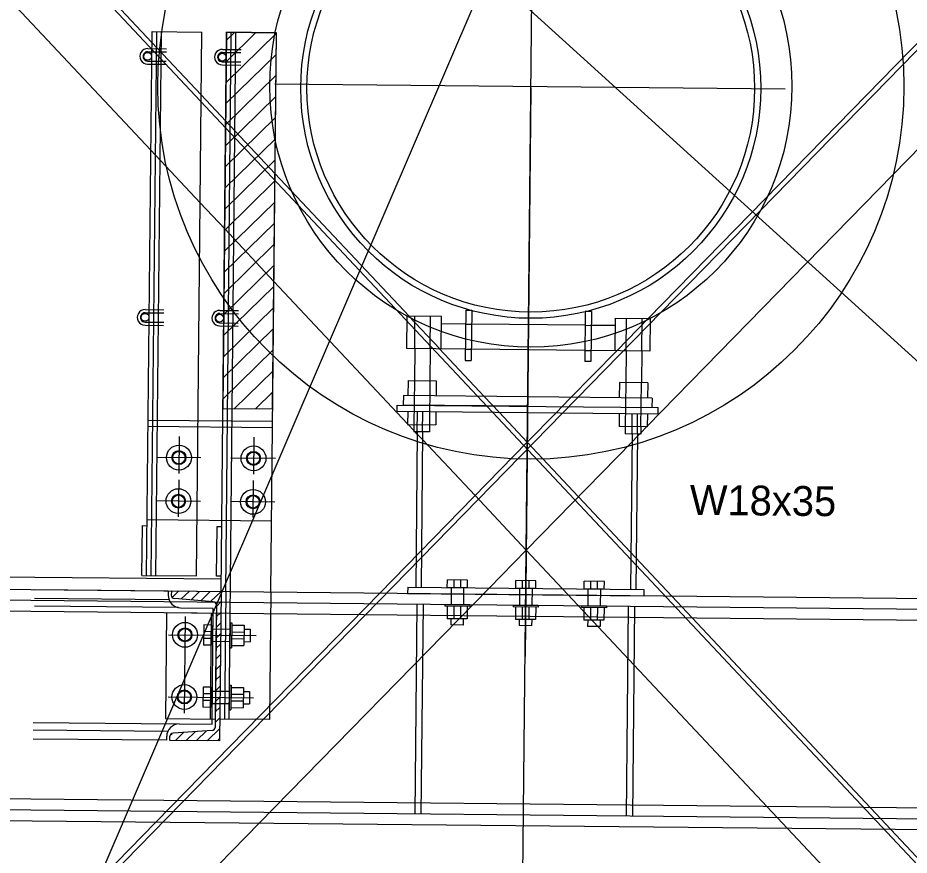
# Model space of a CAD drawing. Extents: x 632312 to 632885, y 378199 to 378534.
# Drawn here: x 632769.45 to 632775.42, y 378346.72 to 378352.33 of the extents above; entities that cross this region are included whole.
import ezdxf

# ---------------------------------------------------------------- set-up
doc = ezdxf.new("R2010")
doc.units = 0
for name, color, linetype in [('B_Boring', 7, 'Continuous'), ('BDR-SHEET_TITLE', 7, 'Continuous'), ('R_Border', 7, 'Continuous'), ('R_Proposed Const Limits', 7, 'Continuous'), ('R_Proposed Const Limits Cut', 7, 'Continuous'), ('R_Road Edge of Shoulder', 7, 'Continuous'), ('R_Wall', 7, 'Continuous'), ('SHT_Dimensions', 7, 'Continuous'), ('USACE_Easement', 7, 'Continuous')]:
    doc.layers.add(name, color=color, linetype=linetype)

msp = doc.modelspace()

# ---------------------------------------------------------------- linework, layer by layer
at = {"layer": 'B_Boring'}
for p, q in [((632770.3098, 378348.5913), (632770.346, 378352.237)), ((632770.341, 378348.591), (632770.3773, 378352.2366)), ((632770.346, 378352.237), (632770.6793, 378352.2336)), ((632770.6431, 378348.588), (632770.6793, 378352.2336)), ((632770.8087, 378348.4822), (632770.846, 378352.232)), ((632770.84, 378348.4819), (632770.8772, 378352.2317)), ((632770.8426, 378351.8956), (632771.1793, 378352.2256)), ((632770.8441, 378352.037), (632771.041, 378352.23)), ((632770.8455, 378352.1784), (632770.8996, 378352.2314)), ((632770.846, 378352.232), (632771.1793, 378352.2287)), ((632771.142, 378348.4789), (632771.1793, 378352.2287)), ((632770.3172, 378352.1226), (632770.4422, 378352.1214)), ((632770.8172, 378352.1177), (632770.9422, 378352.1164)), ((632770.317, 378352.1018), (632770.442, 378352.1006)), ((632770.817, 378352.0968), (632770.942, 378352.0956)), ((632770.8412, 378351.7542), (632771.1779, 378352.0842)), ((632770.3162, 378352.0185), (632770.4412, 378352.0172)), ((632770.3164, 378352.0393), (632770.4414, 378352.0381)), ((632770.8162, 378352.0135), (632770.9412, 378352.0123)), ((632770.8164, 378352.0343), (632770.9414, 378352.0331)), ((632770.8398, 378351.6128), (632771.1765, 378351.9428)), ((632770.8384, 378351.4713), (632771.1751, 378351.8013)), ((632770.837, 378351.3299), (632771.1737, 378351.6599)), ((632770.8356, 378351.1885), (632771.1722, 378351.5185)), ((632770.8342, 378351.0471), (632771.1708, 378351.3771)), ((632770.8328, 378350.9057), (632771.1694, 378351.2357)), ((632770.8314, 378350.7643), (632771.168, 378351.0943)), ((632770.83, 378350.6229), (632771.1666, 378350.9529)), ((632770.8286, 378350.4814), (632771.1652, 378350.8114)), ((632770.8272, 378350.34), (632771.1638, 378350.67)), ((632770.8258, 378350.1986), (632771.1624, 378350.5286)), ((632770.2998, 378350.3727), (632770.4248, 378350.3715)), ((632770.8244, 378350.0572), (632771.161, 378350.3872)), ((632770.2996, 378350.3519), (632770.4246, 378350.3507)), ((632772.0525, 378350.3285), (632772.0504, 378350.1117)), ((632772.2866, 378350.3262), (632772.0525, 378350.3285)), ((632772.2845, 378350.1094), (632772.2866, 378350.3262)), ((632772.4479, 378350.3687), (632772.4445, 378350.0328)), ((632772.4479, 378350.3687), (632772.4889, 378350.3682)), ((632772.4889, 378350.3682), (632772.4856, 378350.0324)), ((632773.2494, 378350.3607), (632773.2461, 378350.0249)), ((632773.2905, 378350.3603), (632773.2494, 378350.3607)), ((632773.2905, 378350.3603), (632773.2872, 378350.0245)), ((632773.4487, 378350.0978), (632773.4509, 378350.3146)), ((632773.4509, 378350.3146), (632773.685, 378350.3123)), ((632770.2988, 378350.2686), (632770.4238, 378350.2673)), ((632770.299, 378350.2894), (632770.424, 378350.2882)), ((632772.447, 378350.2758), (632772.2862, 378350.2774)), ((632773.2485, 378350.2678), (632772.488, 378350.2754)), ((632773.4504, 378350.2658), (632773.2896, 378350.2674)), ((632773.685, 378350.3123), (632773.6828, 378350.0955)), ((632770.823, 378349.9158), (632771.1596, 378350.2458)), ((632770.8216, 378349.7744), (632771.1582, 378350.1044)), ((632772.4453, 378350.1078), (632772.0504, 378350.1117)), ((632772.1059, 378350.1111), (632772.1038, 378349.8976)), ((632772.2107, 378350.1101), (632772.2086, 378349.8966)), ((632773.2468, 378350.0998), (632772.4864, 378350.1074)), ((632773.6828, 378350.0955), (632773.2879, 378350.0994)), ((632773.5225, 378350.0971), (632773.5204, 378349.8836)), ((632773.6273, 378350.096), (632773.6252, 378349.8825)), ((632772.4445, 378350.0328), (632772.4856, 378350.0324)), ((632773.2872, 378350.0245), (632773.2461, 378350.0249)), ((632770.8981, 378349.7094), (632771.1568, 378349.963)), ((632772.0616, 378349.8981), (632772.0606, 378349.7959)), ((632772.0616, 378349.8981), (632772.2508, 378349.8962)), ((632772.2508, 378349.8962), (632772.2497, 378349.7941)), ((632773.4782, 378349.884), (632773.4772, 378349.7819)), ((632773.6674, 378349.8821), (632773.4782, 378349.884)), ((632773.6674, 378349.8821), (632773.6663, 378349.78)), ((632771.0395, 378349.708), (632771.1554, 378349.8215)), ((632772.0302, 378349.7962), (632772.0295, 378349.733)), ((632773.6968, 378349.7797), (632772.0302, 378349.7962)), ((632773.6968, 378349.7797), (632773.6961, 378349.7165)), ((632771.9875, 378349.6918), (632771.9879, 378349.7335)), ((632771.9879, 378349.7335), (632773.7378, 378349.7161)), ((632773.7374, 378349.6744), (632773.7378, 378349.7161)), ((632771.9875, 378349.6918), (632773.7374, 378349.6744)), ((632772.0595, 378349.6911), (632772.0587, 378349.603)), ((632772.2487, 378349.6892), (632772.2478, 378349.6012)), ((632773.4761, 378349.677), (632773.4753, 378349.589)), ((632773.6653, 378349.6751), (632773.6644, 378349.5871)), ((632770.3201, 378349.6329), (632771.1534, 378349.6246)), ((632772.0587, 378349.603), (632772.2478, 378349.6012)), ((632772.1008, 378349.6026), (632772.1004, 378349.5536)), ((632772.2056, 378349.6016), (632772.2052, 378349.5526)), ((632770.3197, 378349.5912), (632771.153, 378349.583)), ((632772.2052, 378349.5526), (632772.1004, 378349.5536)), ((632772.1236, 378349.5534), (632772.1132, 378348.5109)), ((632772.159, 378349.553), (632772.1486, 378348.5105)), ((632773.6644, 378349.5871), (632773.4753, 378349.589)), ((632773.5174, 378349.5885), (632773.517, 378349.5395)), ((632773.6218, 378349.5385), (632773.517, 378349.5395)), ((632773.5631, 378349.5391), (632773.5527, 378348.4966)), ((632773.5985, 378349.5387), (632773.5882, 378348.4962)), ((632773.6222, 378349.5875), (632773.6218, 378349.5385)), ((632770.3135, 378348.9663), (632771.1468, 378348.958)), ((632770.2785, 378348.5916), (632770.2818, 378348.9249)), ((632770.2818, 378348.9249), (632770.3131, 378348.9246)), ((632770.7785, 378348.5866), (632770.7818, 378348.92)), ((632770.7818, 378348.92), (632770.8131, 378348.9196)), ((632770.8095, 378348.5655), (632768.3097, 378348.5904)), ((632770.2785, 378348.5916), (632770.6431, 378348.588)), ((632770.8097, 378348.5863), (632770.7785, 378348.5866)), ((632772.3247, 378348.5088), (632772.3252, 378348.5608)), ((632772.4606, 378348.5595), (632772.3252, 378348.5608)), ((632772.3698, 378348.5083), (632772.3703, 378348.5604)), ((632772.4149, 378348.5079), (632772.4155, 378348.5599)), ((632772.4601, 378348.5074), (632772.4606, 378348.5595)), ((632772.783, 378348.5042), (632772.7835, 378348.5563)), ((632772.9189, 378348.5549), (632772.7835, 378348.5563)), ((632772.8281, 378348.5038), (632772.8286, 378348.5558)), ((632772.8733, 378348.5033), (632772.8738, 378348.5554)), ((632772.9184, 378348.5029), (632772.9189, 378348.5549)), ((632773.2413, 378348.4996), (632773.2418, 378348.5517)), ((632773.3772, 378348.5504), (632773.2418, 378348.5517)), ((632773.2864, 378348.4992), (632773.287, 378348.5513)), ((632773.3316, 378348.4988), (632773.3321, 378348.5508)), ((632773.3767, 378348.4983), (632773.3772, 378348.5504)), ((632778.35, 378348.4072), (632767.3505, 378348.5165)), ((632770.4539, 378348.4857), (632769.5588, 378348.4946)), ((632770.4539, 378348.4857), (632770.4537, 378348.4586)), ((632770.4754, 378348.4855), (632770.4752, 378348.4584)), ((632770.8087, 378348.4822), (632770.4754, 378348.4855)), ((632770.4811, 378348.4436), (632770.5234, 378348.485)), ((632770.542, 378348.4332), (632770.5941, 378348.4843)), ((632770.6074, 378348.4273), (632770.6648, 378348.4836)), ((632770.6729, 378348.4214), (632770.7355, 378348.4829)), ((632770.7383, 378348.4156), (632770.8063, 378348.4822)), ((632770.8087, 378348.4822), (632770.7988, 378347.4822)), ((632772.0591, 378348.5114), (632772.0587, 378348.4697)), ((632772.0587, 378348.4697), (632773.6419, 378348.454)), ((632772.0591, 378348.5114), (632773.6423, 378348.4957)), ((632772.4601, 378348.5074), (632772.3247, 378348.5088)), ((632772.3507, 378348.5085), (632772.3496, 378348.3943)), ((632772.434, 378348.5077), (632772.4329, 378348.3935)), ((632772.9184, 378348.5029), (632772.783, 378348.5042)), ((632772.809, 378348.5039), (632772.8079, 378348.3898)), ((632772.8924, 378348.5031), (632772.8912, 378348.389)), ((632773.3767, 378348.4983), (632773.2413, 378348.4996)), ((632773.2673, 378348.4994), (632773.2662, 378348.3852)), ((632773.3507, 378348.4986), (632773.3495, 378348.3844)), ((632773.6423, 378348.4957), (632773.6419, 378348.454)), ((632778.3493, 378348.3347), (632767.3498, 378348.4441)), ((632770.4594, 378348.4273), (632769.5582, 378348.4363)), ((632770.7564, 378348.4139), (632770.4957, 378348.4374)), ((632770.7769, 378348.3834), (632770.808, 378348.4139)), ((632770.5362, 378348.3745), (632770.7559, 378348.3723)), ((632770.7482, 378347.5931), (632770.7559, 378348.3723)), ((632770.777, 378348.3929), (632770.7688, 378347.5721)), ((632770.7762, 378348.3127), (632770.8073, 378348.3432)), ((632772.3079, 378348.3948), (632772.3078, 378348.3843)), ((632772.4745, 378348.3827), (632772.3078, 378348.3843)), ((632772.4746, 378348.3931), (632772.3079, 378348.3948)), ((632772.3234, 378348.3842), (632772.3226, 378348.3009)), ((632772.3686, 378348.3837), (632772.3677, 378348.3004)), ((632772.4137, 378348.3833), (632772.4129, 378348.3)), ((632772.4588, 378348.3828), (632772.458, 378348.2995)), ((632772.4746, 378348.3931), (632772.4745, 378348.3827)), ((632772.7662, 378348.3902), (632772.7661, 378348.3798)), ((632772.9328, 378348.3781), (632772.7661, 378348.3798)), ((632772.9329, 378348.3885), (632772.7662, 378348.3902)), ((632772.7818, 378348.3796), (632772.7809, 378348.2963)), ((632772.8269, 378348.3792), (632772.8261, 378348.2959)), ((632772.872, 378348.3787), (632772.8712, 378348.2954)), ((632772.9171, 378348.3783), (632772.9163, 378348.295)), ((632772.9329, 378348.3885), (632772.9328, 378348.3781)), ((632773.2245, 378348.3856), (632773.2244, 378348.3752)), ((632773.3911, 378348.3736), (632773.2244, 378348.3752)), ((632773.3912, 378348.384), (632773.2245, 378348.3856)), ((632773.2401, 378348.3751), (632773.2392, 378348.2917)), ((632773.2852, 378348.3746), (632773.2844, 378348.2913)), ((632773.3303, 378348.3742), (632773.3295, 378348.2908)), ((632773.3755, 378348.3737), (632773.3746, 378348.2904)), ((632773.3912, 378348.384), (632773.3911, 378348.3736)), ((632770.4431, 378348.34), (632770.4361, 378347.6317)), ((632770.7764, 378348.3366), (632770.4431, 378348.34)), ((632770.7382, 378347.6287), (632770.7452, 378348.337)), ((632770.7764, 378348.3366), (632770.7694, 378347.6283)), ((632772.458, 378348.2995), (632772.3226, 378348.3009)), ((632772.3486, 378348.3006), (632772.3482, 378348.2589)), ((632772.432, 378348.2998), (632772.4316, 378348.2581)), ((632772.9163, 378348.295), (632772.7809, 378348.2963)), ((632772.807, 378348.296), (632772.8065, 378348.2544)), ((632772.8903, 378348.2952), (632772.8899, 378348.2535)), ((632773.3746, 378348.2904), (632773.2392, 378348.2917)), ((632773.2653, 378348.2915), (632773.2649, 378348.2498)), ((632773.3486, 378348.2907), (632773.3482, 378348.249)), ((632770.6924, 378348.2593), (632770.691, 378348.124)), ((632770.7445, 378348.2588), (632770.6924, 378348.2593)), ((632770.7445, 378348.2588), (632770.7431, 378348.1234)), ((632770.7755, 378348.242), (632770.8066, 378348.2725)), ((632770.8691, 378348.2732), (632770.8675, 378348.1066)), ((632770.8691, 378348.2732), (632770.8796, 378348.2731)), ((632770.8796, 378348.2731), (632770.8779, 378348.1065)), ((632770.8794, 378348.2575), (632770.9627, 378348.2567)), ((632770.9627, 378348.2567), (632770.9614, 378348.1213)), ((632770.9625, 378348.2306), (632771.0041, 378348.2302)), ((632771.0041, 378348.2302), (632771.0033, 378348.1469)), ((632772.4316, 378348.2581), (632772.3482, 378348.2589)), ((632772.8899, 378348.2535), (632772.8065, 378348.2544)), ((632773.3482, 378348.249), (632773.2649, 378348.2498)), ((632770.7436, 378348.1686), (632770.6915, 378348.1691)), ((632770.744, 378348.2137), (632770.6919, 378348.2142)), ((632770.7748, 378348.1713), (632770.8059, 378348.2018)), ((632770.8785, 378348.1672), (632770.9618, 378348.1664)), ((632770.8789, 378348.2124), (632770.9623, 378348.2115)), ((632770.7431, 378348.1234), (632770.691, 378348.124)), ((632770.7741, 378348.1006), (632770.8052, 378348.1311)), ((632770.8675, 378348.1066), (632770.8779, 378348.1065)), ((632770.8781, 378348.1221), (632770.9614, 378348.1213)), ((632770.9616, 378348.1473), (632771.0033, 378348.1469)), ((632770.7734, 378348.0299), (632770.8045, 378348.0604)), ((632770.7727, 378347.9592), (632770.8038, 378347.9897)), ((632770.772, 378347.8884), (632770.8031, 378347.919)), ((632770.6882, 378347.8427), (632770.6869, 378347.7073)), ((632770.7403, 378347.8422), (632770.6882, 378347.8427)), ((632770.7403, 378347.8422), (632770.739, 378347.7068)), ((632770.7713, 378347.8177), (632770.8024, 378347.8483)), ((632770.865, 378347.8566), (632770.8633, 378347.6899)), ((632770.865, 378347.8566), (632770.8754, 378347.8565)), ((632770.8754, 378347.8565), (632770.8738, 378347.6898)), ((632770.8753, 378347.8408), (632770.9586, 378347.84)), ((632770.9586, 378347.84), (632770.9572, 378347.7046)), ((632770.9583, 378347.814), (632771, 378347.8136)), ((632771, 378347.8136), (632770.9992, 378347.7302)), ((632770.7394, 378347.7519), (632770.6873, 378347.7524)), ((632770.7399, 378347.7971), (632770.6878, 378347.7976)), ((632770.7706, 378347.747), (632770.8017, 378347.7776)), ((632770.8744, 378347.7506), (632770.9577, 378347.7497)), ((632770.8748, 378347.7957), (632770.9581, 378347.7949)), ((632770.739, 378347.7068), (632770.6869, 378347.7073)), ((632770.7699, 378347.6763), (632770.801, 378347.7068)), ((632770.8633, 378347.6899), (632770.8738, 378347.6898)), ((632770.8739, 378347.7054), (632770.9572, 378347.7046)), ((632770.9575, 378347.7307), (632770.9992, 378347.7302)), ((632770.4361, 378347.6317), (632770.7694, 378347.6283)), ((632770.7692, 378347.6056), (632770.8003, 378347.6361)), ((632770.5284, 378347.5953), (632770.7482, 378347.5931)), ((632770.7156, 378347.483), (632770.7996, 378347.5654)), ((632770.4507, 378347.544), (632769.5494, 378347.553)), ((632770.444, 378347.4857), (632770.4443, 378347.5128)), ((632770.4655, 378347.4855), (632770.4657, 378347.5126)), ((632770.4669, 378347.5194), (632770.48, 378347.5322)), ((632770.7478, 378347.5515), (632770.4867, 378347.5332)), ((632770.5034, 378347.4852), (632770.5575, 378347.5382)), ((632770.5741, 378347.4844), (632770.6344, 378347.5436)), ((632770.6448, 378347.4837), (632770.7113, 378347.5489)), ((632770.444, 378347.4857), (632769.5489, 378347.4946)), ((632770.7988, 378347.4822), (632770.4655, 378347.4855)), ((632770.7988, 378347.4822), (632770.4655, 378347.4855)), ((632770.7863, 378347.4823), (632770.7989, 378347.4947)), ((632770.7956, 378347.4822), (632770.7988, 378347.4853)), ((632778.3353, 378346.9298), (632767.3359, 378347.0391)), ((632778.3346, 378346.8573), (632767.3351, 378346.9666))]:
    msp.add_line(p, q, dxfattribs=at)
for points in [[(632770.3381, 378351.4407), (632768.359, 378353.5494), (632768.7235, 378353.8916), (632770.3453, 378352.1637)], [(632773.6645, 378349.5915), (632777.4419, 378353.4591), (632777.0842, 378353.8084), (632773.6696, 378350.3124)], [(632770.6751, 378351.8122), (632770.8401, 378351.6365)], [(632771.1699, 378351.2851), (632772.0679, 378350.3283)], [(632770.8329, 378350.9135), (632770.668, 378351.0893)], [(632772.0587, 378349.6075), (632771.1627, 378350.5621)], [(632772.2733, 378350.1095), (632772.5723, 378349.7908)], [(632773.4599, 378350.0977), (632773.1445, 378349.7747)], [(632773.0531, 378349.6812), (632772.8604, 378349.4839), (632771.8717, 378348.4716)], [(632772.6717, 378349.685), (632772.8604, 378349.4839)], [(632772.1005, 378349.563), (632772.0629, 378349.603)], [(632772.1234, 378349.5385), (632772.1094, 378349.5535)], [(632773.5984, 378349.5239), (632773.6127, 378349.5386)], [(632773.6218, 378349.5479), (632773.6602, 378349.5871)], [(632772.5107, 378349.1259), (632772.1585, 378349.5012)], [(632772.6042, 378348.506), (632772.8532, 378348.7609), (632773.5626, 378349.4872)], [(632773.2029, 378349.119), (632773.8288, 378348.4521)], [(632773.0972, 378348.5011), (632772.8532, 378348.7609)], [(632770.3724, 378346.9364), (632768.2718, 378344.7858)], [(632768.6295, 378344.4364), (632771.0645, 378346.9295)], [(632776.9901, 378344.3533), (632774.6052, 378346.8943)], [(632775.2974, 378346.8875), (632777.3547, 378344.6955)]]:
    msp.add_lwpolyline(points, dxfattribs=at)
msp.add_lwpolyline([(632771.1793, 378352.2287), (632770.846, 378352.232), (632770.8209, 378349.7102), (632771.1542, 378349.7068)], close=True, dxfattribs=at)
for centre, radius in [((632772.884, 378351.8564), 1.5417), ((632772.884, 378351.8564), 1.5), ((632770.3167, 378352.0706), 0.0261), ((632770.2993, 378350.3207), 0.0261), ((632770.526, 378349.3809), 0.0469), ((632771.0259, 378349.3759), 0.0469), ((632770.5231, 378349.0892), 0.0469), ((632771.023, 378349.0842), 0.0469), ((632770.5667, 378348.1929), 0.0469), ((632770.5625, 378347.7762), 0.0469)]:
    msp.add_circle(centre, radius, dxfattribs=at)
for centre, radius, start, end in [((632770.3167, 378352.0706), 0.0521, 89.43036, 269.43036), ((632770.8167, 378352.0656), 0.0521, 89.43036, 269.43036), ((632770.3167, 378352.0706), 0.0312, 89.43036, 269.43036), ((632770.8167, 378352.0656), 0.0312, 89.43036, 269.43036), ((632770.2993, 378350.3207), 0.0521, 89.43036, 269.43036), ((632770.2993, 378350.3207), 0.0312, 89.43036, 269.43036), ((632770.537, 378348.4578), 0.0833, 179.43036, 269.43036), ((632770.496, 378348.4582), 0.0208, 179.4219, 269.43036), ((632770.7562, 378348.3931), 0.0208, 359.43036, 89.43036), ((632770.5276, 378347.512), 0.0833, 89.43036, 179.43036), ((632770.748, 378347.5723), 0.0208, 269.43036, 359.43036), ((632770.4865, 378347.5124), 0.0208, 89.43036, 179.43036)]:
    msp.add_arc(centre, radius, start, end, dxfattribs=at)
at = {"layer": 'BDR-SHEET_TITLE'}
for p, q in [((632770.5274, 378349.5233), (632770.5249, 378349.2752)), ((632771.0274, 378349.5183), (632771.0249, 378349.2702)), ((632770.6726, 378349.3794), (632770.375, 378349.3824)), ((632771.1726, 378349.3744), (632770.875, 378349.3774)), ((632770.5245, 378349.2317), (632770.522, 378348.9835)), ((632771.0245, 378349.2267), (632771.022, 378348.9786)), ((632770.6697, 378349.0877), (632770.3721, 378349.0907)), ((632771.1697, 378349.0828), (632770.8721, 378349.0857))]:
    msp.add_line(p, q, dxfattribs=at)
at = {"layer": 'R_Border'}
for radius in [2.5, 1.75]:
    msp.add_circle((632772.8842, 378351.8705), radius, dxfattribs=at)
at = {"layer": 'R_Proposed Const Limits'}
msp.add_arc((632770.537, 378348.4578), 0.0833, 179.43036, 269.43036, dxfattribs=at)
at = {"layer": 'R_Proposed Const Limits Cut'}
for p, q in [((632768.7008, 378353.8702), (632777.3319, 378344.6741)), ((632777.1065, 378353.7866), (632768.2942, 378344.7639)), ((632770.3723, 378348.5907), (632770.4085, 378352.2363)), ((632770.8627, 378347.6274), (632770.9085, 378352.2314)), ((632770.6751, 378351.8122), (632770.3453, 378352.1637)), ((632770.8401, 378351.6365), (632771.1699, 378351.2851)), ((632770.668, 378351.0893), (632770.3381, 378351.4407)), ((632770.8329, 378350.9135), (632771.1627, 378350.5621)), ((632772.2745, 378350.1095), (632772.0678, 378350.3283)), ((632772.1059, 378350.1111), (632772.1081, 378350.3279)), ((632772.2107, 378350.1101), (632772.2129, 378350.3269)), ((632773.5225, 378350.0971), (632773.5247, 378350.3138)), ((632773.6273, 378350.096), (632773.6294, 378350.3128)), ((632772.447, 378350.2758), (632772.488, 378350.2754)), ((632773.2485, 378350.2678), (632773.2896, 378350.2674)), ((632773.4599, 378350.0977), (632773.6696, 378350.3124)), ((632772.4453, 378350.1078), (632772.4864, 378350.1074)), ((632773.2468, 378350.0998), (632773.2879, 378350.0994)), ((632772.1038, 378349.8976), (632772.1008, 378349.6026)), ((632772.2086, 378349.8966), (632772.2056, 378349.6016)), ((632773.5204, 378349.8836), (632773.5174, 378349.5885)), ((632773.6222, 378349.5875), (632773.6252, 378349.8825)), ((632772.6717, 378349.685), (632772.5723, 378349.7908)), ((632773.0531, 378349.6812), (632773.1445, 378349.7747)), ((632772.1236, 378349.5534), (632772.125, 378349.6904)), ((632772.159, 378349.553), (632772.1604, 378349.6901)), ((632773.5631, 378349.5391), (632773.5645, 378349.6761)), ((632773.5985, 378349.5387), (632773.5999, 378349.6758)), ((632772.0587, 378349.6075), (632772.0629, 378349.603)), ((632772.1005, 378349.563), (632772.1094, 378349.5535)), ((632772.1234, 378349.5385), (632772.1585, 378349.5012)), ((632773.6127, 378349.5386), (632773.6218, 378349.5479)), ((632773.6602, 378349.5871), (632773.6645, 378349.5915)), ((632773.2029, 378349.119), (632772.8604, 378349.4839)), ((632773.5626, 378349.4872), (632773.5984, 378349.5239)), ((632772.5107, 378349.1259), (632772.8532, 378348.7609)), ((632771.8717, 378348.4716), (632770.3724, 378346.9364)), ((632770.84, 378348.4819), (632770.8315, 378347.6277)), ((632771.0645, 378346.9295), (632772.6042, 378348.506)), ((632771.142, 378348.4789), (632771.1335, 378347.6247)), ((632773.0972, 378348.5011), (632774.6052, 378346.8943)), ((632773.8288, 378348.4521), (632775.2974, 378346.8875)), ((632778.3486, 378348.2614), (632767.3491, 378348.3707)), ((632770.5231, 378348.3756), (632769.5577, 378348.3852)), ((632770.7442, 378348.2328), (632770.8687, 378348.2316)), ((632770.7434, 378348.1495), (632770.8679, 378348.1482)), ((632770.7401, 378347.8161), (632770.8646, 378347.8149)), ((632770.7392, 378347.7328), (632770.8638, 378347.7316)), ((632771.1335, 378347.6247), (632770.8002, 378347.628)), ((632770.5153, 378347.5944), (632769.5499, 378347.604)), ((632778.336, 378347.0031), (632767.3366, 378347.1125))]:
    msp.add_line(p, q, dxfattribs=at)
for centre, radius in [((632770.526, 378349.3809), 0.0833), ((632770.526, 378349.3809), 0.0417), ((632771.0259, 378349.3759), 0.0833), ((632771.0259, 378349.3759), 0.0417), ((632770.5231, 378349.0892), 0.0833), ((632770.5231, 378349.0892), 0.0417), ((632771.023, 378349.0842), 0.0833), ((632771.023, 378349.0842), 0.0417), ((632770.5667, 378348.1929), 0.0833), ((632770.5667, 378348.1929), 0.0417), ((632770.5625, 378347.7762), 0.0833), ((632770.5625, 378347.7762), 0.0417)]:
    msp.add_circle(centre, radius, dxfattribs=at)
at = {"layer": 'R_Road Edge of Shoulder'}
msp.add_line((632772.7538, 378338.7619), (632773.0843, 378372.0036), dxfattribs=at)
at = {"layer": 'R_Wall'}
for p, q in [((632770.5679, 378348.3157), (632770.5614, 378347.6675)), ((632770.4573, 378348.194), (632771.0433, 378348.1882)), ((632770.4542, 378347.7773), (632771.0269, 378347.7716))]:
    msp.add_line(p, q, dxfattribs=at)
at = {"layer": 'SHT_Dimensions'}
for p, q in [((632771.1685, 378351.8875), (632774.589, 378351.8535)), ((632772.8841, 378351.8601), (632772.8462, 378348.0485)), ((632770.7996, 378350.3469), (632770.9246, 378350.3457)), ((632770.7998, 378350.3678), (632770.9248, 378350.3665)), ((632770.7988, 378350.2636), (632770.9238, 378350.2624)), ((632770.799, 378350.2844), (632770.924, 378350.2832)), ((632772.8628, 378349.7248), (632772.0295, 378349.733)), ((632772.1204, 378348.3966), (632772.1065, 378346.9917)), ((632772.1621, 378348.3962), (632772.1481, 378346.9913)), ((632773.537, 378348.3825), (632773.5231, 378346.9776)), ((632773.5787, 378348.3821), (632773.5647, 378346.9772))]:
    msp.add_line(p, q, dxfattribs=at)
for centre in [(632770.8167, 378352.0656), (632770.7993, 378350.3157)]:
    msp.add_circle(centre, 0.0261, dxfattribs=at)
for radius in [0.0521, 0.0312]:
    msp.add_arc((632770.7993, 378350.3157), radius, 89.43036, 269.43036, dxfattribs=at)
at = {"layer": 'USACE_Easement'}
for p, q in [((632765.668, 378336.4864), (632777.7733, 378364.6944)), ((632763.7089, 378360.7088), (632793.4152, 378333.7352))]:
    msp.add_line(p, q, dxfattribs=at)

# ---------------------------------------------------------------- texts
at = {"layer": 'SHT_Dimensions'}
msp.add_text('W18x35', height=0.2, rotation=359.43036, dxfattribs=at).set_placement((632773.9488, 378348.9978))

doc.saveas('drawing.dxf')
